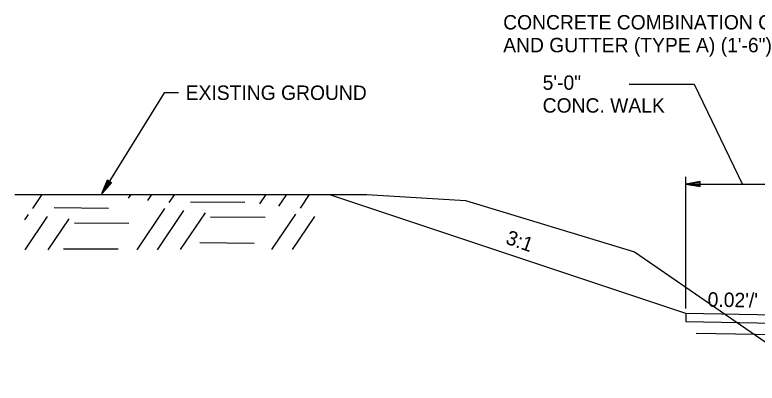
# Model space of a CAD drawing. Extents: x 1001270 to 1003428, y 1840152 to 1842912.
# Drawn here: x 1001296.34 to 1001327.23, y 1840303.68 to 1840319.02 of the extents above; entities that cross this region are included whole.
import ezdxf

# ---------------------------------------------------------------- set-up
doc = ezdxf.new("R2010")
doc.units = 0
doc.layers.add('19', color=7, linetype='Continuous')
doc.layers.add('20', color=7, linetype='Continuous')

msp = doc.modelspace()

# ---------------------------------------------------------------- linework, layer by layer
at = {"layer": '19'}
for p, q in [((1001321.902, 1840316.13), (1001324.613, 1840316.13)), ((1001324.613, 1840316.13), (1001326.626, 1840311.959)), ((1001299.97, 1840311.575), (1001300.193, 1840312.141)), ((1001300.044, 1840311.715), (1001300.236, 1840312.109)), ((1001300.33, 1840312.053), (1001300.066, 1840311.704)), ((1001300.193, 1840312.141), (1001300.371, 1840312.032)), ((1001324.267, 1840306.791), (1001324.267, 1840312.273)), ((1001324.867, 1840312.078), (1001324.267, 1840311.973)), ((1001324.867, 1840311.868), (1001324.867, 1840312.078)), ((1001300.371, 1840312.032), (1001299.97, 1840311.575)), ((1001324.267, 1840311.973), (1001333.767, 1840311.973)), ((1001324.267, 1840311.973), (1001324.867, 1840311.868)), ((1001324.867, 1840312.023), (1001324.427, 1840311.988)), ((1001324.427, 1840311.958), (1001324.867, 1840311.918)), ((1001296.344, 1840311.533), (1001310.994, 1840311.536)), ((1001297.094, 1840310.951), (1001297.486, 1840311.534)), ((1001301.08, 1840311.385), (1001301.186, 1840311.535)), ((1001301.874, 1840311.293), (1001302.04, 1840311.537)), ((1001302.77, 1840311.201), (1001302.996, 1840311.54)), ((1001306.534, 1840311.145), (1001306.796, 1840311.541)), ((1001307.329, 1840311.054), (1001307.66, 1840311.542)), ((1001308.224, 1840310.961), (1001308.605, 1840311.535)), ((1001324.26, 1840306.589), (1001309.494, 1840311.511)), ((1001303.657, 1840311.23), (1001305.918, 1840311.219)), ((1001297.983, 1840310.99), (1001300.243, 1840310.969)), ((1001301.432, 1840309.238), (1001302.584, 1840310.959)), ((1001302.286, 1840309.24), (1001303.379, 1840310.867)), ((1001296.755, 1840310.483), (1001296.909, 1840310.708)), ((1001296.777, 1840309.234), (1001297.703, 1840310.617)), ((1001297.732, 1840309.236), (1001298.599, 1840310.524)), ((1001303.242, 1840309.242), (1001304.274, 1840310.775)), ((1001304.487, 1840310.602), (1001306.758, 1840310.59)), ((1001307.042, 1840309.243), (1001308.038, 1840310.719)), ((1001307.897, 1840309.246), (1001308.833, 1840310.627)), ((1001298.823, 1840310.361), (1001301.083, 1840310.339)), ((1001298.37, 1840309.281), (1001300.641, 1840309.269)), ((1001304.046, 1840309.532), (1001306.305, 1840309.51)), ((1001329.259, 1840306.49), (1001324.26, 1840306.589)), ((1001324.26, 1840306.589), (1001324.26, 1840306.256)), ((1001324.26, 1840306.256), (1001329.259, 1840306.156))]:
    msp.add_line(p, q, dxfattribs=at)
for points in [[(1001303.153, 1840315.774), (1001302.553, 1840315.773), (1001299.97, 1840311.575)], [(1001310.994, 1840311.536), (1001315.095, 1840311.288), (1001322.129, 1840309.145), (1001325.915, 1840306.542)], [(1001325.915, 1840306.542), (1001329.702, 1840303.938), (1001331.999, 1840303.684)]]:
    msp.add_lwpolyline(points, dxfattribs=at)
at = {"layer": '20'}
msp.add_line((1001324.697, 1840305.77), (1001327.967, 1840305.705), dxfattribs=at)

# ---------------------------------------------------------------- texts
at = {"layer": '19'}
for s, rotation, p in [('CONCRETE COMBINATION CURB', 360, (1001316.664, 1840318.406)), ('AND GUTTER (TYPE A) (1\'-6")', 360, (1001316.664, 1840317.456)), ('5\'-0"', 360, (1001318.306, 1840315.894)), ('CONC. WALK', 360, (1001318.306, 1840314.944)), ('3:1', 340.4943, (1001316.728, 1840309.504)), ("0.02'/'", 358.8581, (1001325.167, 1840306.871))]:
    msp.add_text(s, height=0.6, rotation=rotation, dxfattribs=at).set_placement(p)
msp.add_text('EXISTING GROUND', height=0.6, dxfattribs=at).set_placement((1001303.453, 1840315.474))

doc.saveas('drawing.dxf')
